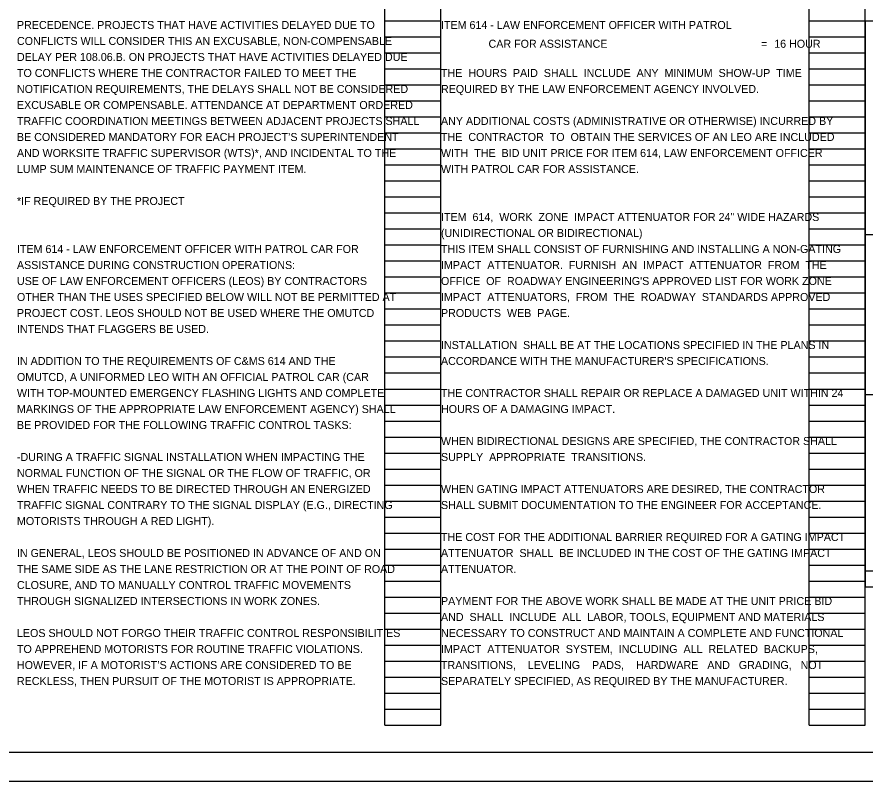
# Model space of a CAD drawing. Extents: x -7.9 to 64.5, y -13.1 to 23.6.
# Drawn here: x 2.4 to 17.24, y 0 to 13.37 of the extents above; entities that cross this region are included whole.
import ezdxf

# ---------------------------------------------------------------- set-up
doc = ezdxf.new("R2010")
doc.units = 0
for name, color, linetype in [('SH_Border', 7, 'Continuous'), ('SH_Cut_Line', 7, 'Continuous'), ('SH_Data', 7, 'Continuous'), ('SH_Text', 7, 'Continuous')]:
    doc.layers.add(name, color=color, linetype=linetype)

msp = doc.modelspace()

# ---------------------------------------------------------------- linework, layer by layer
at = {"layer": 'SH_Border'}
msp.add_lwpolyline([(1.5, 21.5), (33.5, 21.5), (33.5, 0.5), (1.5, 0.5)], close=True, dxfattribs=at)
at = {"layer": 'SH_Cut_Line'}
msp.add_lwpolyline([(0, 0), (34, 0), (34, 22), (0, 22)], close=True, dxfattribs=at)
at = {"layer": 'SH_Data'}
for p, q in [((8.84, 0.98), (8.84, 21.14)), ((9.82, 0.98), (9.82, 21.14)), ((16.26, 0.98), (16.26, 21.14)), ((17.24, 0.98), (17.24, 21.14)), ((8.84, 13.3), (9.82, 13.3)), ((16.26, 13.3), (17.24, 13.3)), ((8.84, 13.02), (9.82, 13.02)), ((16.26, 13.02), (17.24, 13.02)), ((8.84, 12.74), (9.82, 12.74)), ((16.26, 12.74), (17.24, 12.74)), ((8.84, 12.46), (9.82, 12.46)), ((16.26, 12.46), (17.24, 12.46)), ((8.84, 12.18), (9.82, 12.18)), ((16.26, 12.18), (17.24, 12.18)), ((8.84, 11.9), (9.82, 11.9)), ((16.26, 11.9), (17.24, 11.9)), ((8.84, 11.62), (9.82, 11.62)), ((16.26, 11.62), (17.24, 11.62)), ((8.84, 11.34), (9.82, 11.34)), ((16.26, 11.34), (17.24, 11.34)), ((8.84, 11.06), (9.82, 11.06)), ((16.26, 11.06), (17.24, 11.06)), ((8.84, 10.78), (9.82, 10.78)), ((16.26, 10.78), (17.24, 10.78)), ((8.84, 10.5), (9.82, 10.5)), ((16.26, 10.5), (17.24, 10.5)), ((8.84, 10.22), (9.82, 10.22)), ((16.26, 10.22), (17.24, 10.22)), ((8.84, 9.94), (9.82, 9.94)), ((16.26, 9.94), (17.24, 9.94)), ((8.84, 9.66), (9.82, 9.66)), ((16.26, 9.66), (17.24, 9.66)), ((8.84, 9.38), (9.82, 9.38)), ((16.26, 9.38), (17.24, 9.38)), ((8.84, 9.1), (9.82, 9.1)), ((16.26, 9.1), (17.24, 9.1)), ((8.84, 8.82), (9.82, 8.82)), ((16.26, 8.82), (17.24, 8.82)), ((8.84, 8.54), (9.82, 8.54)), ((16.26, 8.54), (17.24, 8.54)), ((8.84, 8.26), (9.82, 8.26)), ((16.26, 8.26), (17.24, 8.26)), ((8.84, 7.98), (9.82, 7.98)), ((16.26, 7.98), (17.24, 7.98)), ((8.84, 7.7), (9.82, 7.7)), ((16.26, 7.7), (17.24, 7.7)), ((8.84, 7.42), (9.82, 7.42)), ((16.26, 7.42), (17.24, 7.42)), ((8.84, 7.14), (9.82, 7.14)), ((16.26, 7.14), (17.24, 7.14)), ((8.84, 6.86), (9.82, 6.86)), ((16.26, 6.86), (17.24, 6.86)), ((8.84, 6.58), (9.82, 6.58)), ((16.26, 6.58), (17.24, 6.58)), ((8.84, 6.3), (9.82, 6.3)), ((16.26, 6.3), (17.24, 6.3)), ((8.84, 6.02), (9.82, 6.02)), ((16.26, 6.02), (17.24, 6.02)), ((8.84, 5.74), (9.82, 5.74)), ((16.26, 5.74), (17.24, 5.74)), ((8.84, 5.46), (9.82, 5.46)), ((16.26, 5.46), (17.24, 5.46)), ((8.84, 5.18), (9.82, 5.18)), ((16.26, 5.18), (17.24, 5.18)), ((8.84, 4.9), (9.82, 4.9)), ((16.26, 4.9), (17.24, 4.9)), ((8.84, 4.62), (9.82, 4.62)), ((16.26, 4.62), (17.24, 4.62)), ((8.84, 4.34), (9.82, 4.34)), ((16.26, 4.34), (17.24, 4.34)), ((8.84, 4.06), (9.82, 4.06)), ((16.26, 4.06), (17.24, 4.06)), ((8.84, 3.78), (9.82, 3.78)), ((16.26, 3.78), (17.24, 3.78)), ((8.84, 3.5), (9.82, 3.5)), ((16.26, 3.5), (17.24, 3.5)), ((8.84, 3.22), (9.82, 3.22)), ((16.26, 3.22), (17.24, 3.22)), ((8.84, 2.94), (9.82, 2.94)), ((16.26, 2.94), (17.24, 2.94)), ((8.84, 2.66), (9.82, 2.66)), ((16.26, 2.66), (17.24, 2.66)), ((8.84, 2.38), (9.82, 2.38)), ((16.26, 2.38), (17.24, 2.38)), ((8.84, 2.1), (9.82, 2.1)), ((16.26, 2.1), (17.24, 2.1)), ((8.84, 1.82), (9.82, 1.82)), ((16.26, 1.82), (17.24, 1.82)), ((8.84, 1.54), (9.82, 1.54)), ((16.26, 1.54), (17.24, 1.54)), ((8.84, 1.26), (9.82, 1.26)), ((16.26, 1.26), (17.24, 1.26)), ((8.84, 0.98), (9.82, 0.98)), ((16.26, 0.98), (17.24, 0.98))]:
    msp.add_line(p, q, dxfattribs=at)
at = {"layer": 'SH_Text'}
for p, q in [((17.24, 13.3), (26.776, 13.3)), ((17.24, 13.3), (17.24, 3.401)), ((17.24, 9.561), (18.393, 9.561)), ((17.24, 6.761), (26.776, 6.761)), ((17.24, 3.681), (26.776, 3.681)), ((17.24, 3.401), (26.776, 3.401))]:
    msp.add_line(p, q, dxfattribs=at)

# ---------------------------------------------------------------- texts
for s, p in [('PRECEDENCE. PROJECTS THAT HAVE ACTIVITIES DELAYED DUE TO ', (2.4, 13.16)), ('ITEM 614 - LAW ENFORCEMENT OFFICER WITH PATROL', (9.82, 13.16)), ('CONFLICTS WILL CONSIDER THIS AN EXCUSABLE, NON-COMPENSABLE ', (2.4, 12.88)), ('                CAR FOR ASSISTANCE', (9.82, 12.831)), ('=', (15.421, 12.831)), ('16 HOUR', (15.651, 12.831)), ('DELAY PER 108.06.B. ON PROJECTS THAT HAVE ACTIVITIES DELAYED DUE ', (2.4, 12.6)), ('TO CONFLICTS WHERE THE CONTRACTOR FAILED TO MEET THE ', (2.4, 12.32)), ('THE  HOURS  PAID  SHALL  INCLUDE  ANY  MINIMUM  SHOW-UP  TIME', (9.82, 12.32)), ('NOTIFICATION REQUIREMENTS, THE DELAYS SHALL NOT BE CONSIDERED ', (2.4, 12.04)), ('REQUIRED BY THE LAW ENFORCEMENT AGENCY INVOLVED.', (9.82, 12.04)), ('EXCUSABLE OR COMPENSABLE. ATTENDANCE AT DEPARTMENT ORDERED ', (2.4, 11.76)), ('TRAFFIC COORDINATION MEETINGS BETWEEN ADJACENT PROJECTS SHALL ', (2.4, 11.48)), ('ANY ADDITIONAL COSTS (ADMINISTRATIVE OR OTHERWISE) INCURRED BY', (9.82, 11.48)), ('BE CONSIDERED MANDATORY FOR EACH PROJECT’S SUPERINTENDENT ', (2.4, 11.2)), ('THE  CONTRACTOR  TO  OBTAIN THE SERVICES OF AN LEO ARE INCLUDED', (9.82, 11.2)), ('AND WORKSITE TRAFFIC SUPERVISOR (WTS)*, AND INCIDENTAL TO THE ', (2.4, 10.92)), ('WITH  THE  BID UNIT PRICE FOR ITEM 614, LAW ENFORCEMENT OFFICER', (9.82, 10.92)), ('LUMP SUM MAINTENANCE OF TRAFFIC PAYMENT ITEM.', (2.4, 10.64)), ('WITH PATROL CAR FOR ASSISTANCE.', (9.82, 10.64)), ('*IF REQUIRED BY THE PROJECT', (2.4, 10.08)), ('ITEM  614,  WORK  ZONE  IMPACT ATTENUATOR FOR 24" WIDE HAZARDS', (9.82, 9.8)), ('(UNIDIRECTIONAL OR BIDIRECTIONAL)', (9.82, 9.52)), ('ITEM 614 - LAW ENFORCEMENT OFFICER WITH PATROL CAR FOR ', (2.4, 9.24)), ('THIS ITEM SHALL CONSIST OF FURNISHING AND INSTALLING A NON-GATING', (9.82, 9.24)), ('ASSISTANCE DURING CONSTRUCTION OPERATIONS:', (2.4, 8.96)), ('IMPACT  ATTENUATOR.  FURNISH  AN  IMPACT  ATTENUATOR  FROM  THE', (9.82, 8.96)), ('USE OF LAW ENFORCEMENT OFFICERS (LEOS) BY CONTRACTORS ', (2.4, 8.68)), ("OFFICE  OF  ROADWAY ENGINEERING'S APPROVED LIST FOR WORK ZONE", (9.82, 8.68)), ('OTHER THAN THE USES SPECIFIED BELOW WILL NOT BE PERMITTED AT ', (2.4, 8.4)), ('IMPACT  ATTENUATORS,  FROM  THE  ROADWAY  STANDARDS APPROVED', (9.82, 8.4)), ('PROJECT COST. LEOS SHOULD NOT BE USED WHERE THE OMUTCD ', (2.4, 8.12)), ('PRODUCTS  WEB  PAGE.', (9.82, 8.12)), ('INTENDS THAT FLAGGERS BE USED.', (2.4, 7.84)), ('INSTALLATION  SHALL BE AT THE LOCATIONS SPECIFIED IN THE PLANS IN', (9.82, 7.56)), ('IN ADDITION TO THE REQUIREMENTS OF C&MS 614 AND THE ', (2.4, 7.28)), ("ACCORDANCE WITH THE MANUFACTURER'S SPECIFICATIONS.", (9.82, 7.28)), ('OMUTCD, A UNIFORMED LEO WITH AN OFFICIAL PATROL CAR (CAR ', (2.4, 7)), ('WITH TOP-MOUNTED EMERGENCY FLASHING LIGHTS AND COMPLETE ', (2.4, 6.72)), ('THE CONTRACTOR SHALL REPAIR OR REPLACE A DAMAGED UNIT WITHIN 24', (9.82, 6.72)), ('MARKINGS OF THE APPROPRIATE LAW ENFORCEMENT AGENCY) SHALL ', (2.4, 6.44)), ('HOURS OF A DAMAGING IMPACT.', (9.82, 6.44)), ('BE PROVIDED FOR THE FOLLOWING TRAFFIC CONTROL TASKS:', (2.4, 6.16)), ('WHEN BIDIRECTIONAL DESIGNS ARE SPECIFIED, THE CONTRACTOR SHALL', (9.82, 5.88)), ('-DURING A TRAFFIC SIGNAL INSTALLATION WHEN IMPACTING THE ', (2.4, 5.6)), ('SUPPLY  APPROPRIATE  TRANSITIONS.', (9.82, 5.6)), ('NORMAL FUNCTION OF THE SIGNAL OR THE FLOW OF TRAFFIC, OR ', (2.4, 5.32)), ('WHEN TRAFFIC NEEDS TO BE DIRECTED THROUGH AN ENERGIZED ', (2.4, 5.04)), ('WHEN GATING IMPACT ATTENUATORS ARE DESIRED, THE CONTRACTOR', (9.82, 5.04)), ('TRAFFIC SIGNAL CONTRARY TO THE SIGNAL DISPLAY (E.G., DIRECTING ', (2.4, 4.76)), ('SHALL SUBMIT DOCUMENTATION TO THE ENGINEER FOR ACCEPTANCE.', (9.82, 4.76)), ('MOTORISTS THROUGH A RED LIGHT). ', (2.4, 4.48)), ('THE COST FOR THE ADDITIONAL BARRIER REQUIRED FOR A GATING IMPACT', (9.82, 4.2)), ('IN GENERAL, LEOS SHOULD BE POSITIONED IN ADVANCE OF AND ON ', (2.4, 3.92)), ('ATTENUATOR  SHALL  BE INCLUDED IN THE COST OF THE GATING IMPACT', (9.82, 3.92)), ('THE SAME SIDE AS THE LANE RESTRICTION OR AT THE POINT OF ROAD ', (2.4, 3.64)), ('ATTENUATOR.', (9.82, 3.64)), ('CLOSURE, AND TO MANUALLY CONTROL TRAFFIC MOVEMENTS ', (2.4, 3.36)), ('THROUGH SIGNALIZED INTERSECTIONS IN WORK ZONES. ', (2.4, 3.08)), ('PAYMENT FOR THE ABOVE WORK SHALL BE MADE AT THE UNIT PRICE BID', (9.82, 3.08)), ('AND  SHALL  INCLUDE  ALL  LABOR, TOOLS, EQUIPMENT AND MATERIALS', (9.82, 2.8)), ('LEOS SHOULD NOT FORGO THEIR TRAFFIC CONTROL RESPONSIBILITIES ', (2.4, 2.52)), ('NECESSARY TO CONSTRUCT AND MAINTAIN A COMPLETE AND FUNCTIONAL', (9.82, 2.52)), ('TO APPREHEND MOTORISTS FOR ROUTINE TRAFFIC VIOLATIONS. ', (2.4, 2.24)), ('IMPACT  ATTENUATOR  SYSTEM,  INCLUDING  ALL  RELATED  BACKUPS,', (9.82, 2.24)), ('HOWEVER, IF A MOTORIST’S ACTIONS ARE CONSIDERED TO BE ', (2.4, 1.96)), ('TRANSITIONS,    LEVELING    PADS,    HARDWARE   AND   GRADING,   NOT', (9.82, 1.96)), ('RECKLESS, THEN PURSUIT OF THE MOTORIST IS APPROPRIATE. ', (2.4, 1.68)), ('SEPARATELY SPECIFIED, AS REQUIRED BY THE MANUFACTURER.', (9.82, 1.68))]:
    msp.add_text(s, height=0.14, dxfattribs=at).set_placement(p)

doc.saveas('drawing.dxf')
